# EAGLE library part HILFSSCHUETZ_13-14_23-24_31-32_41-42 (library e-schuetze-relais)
Hilfsschütz mit 2 Schließern, 2 Öffnern
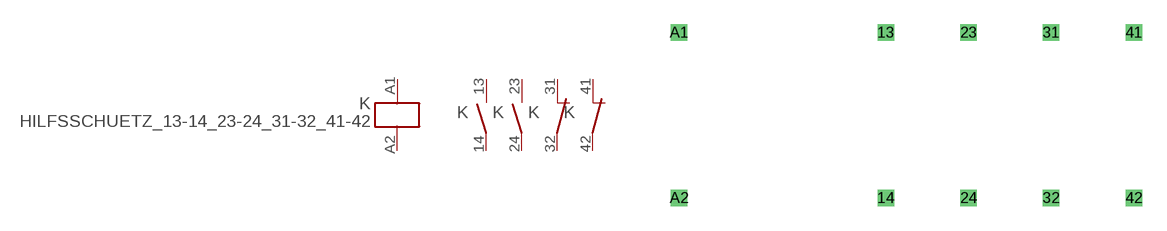
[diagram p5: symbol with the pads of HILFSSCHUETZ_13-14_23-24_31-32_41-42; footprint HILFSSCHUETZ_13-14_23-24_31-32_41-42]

Designator prefix K; gates G$1=SPULE 1=SCHLIESSER 2=SCHLIESSER 3=OEFFNER 4=OEFFNER

## HILFSSCHUETZ_13-14_23-24_31-32_41-42  [HILFSSCHUETZ_13-14_23-24_31-32_41-42]
13  1:3  pas
14  1:4  pas
23  2:3  pas
24  2:4  pas
31  3:1  pas
32  3:2  pas
41  4:1  pas
42  4:2  pas
A1  G$1:A1  in
A2  G$1:A2  in

## Footprint HILFSSCHUETZ_13-14_23-24_31-32_41-42 (pad centres in mm)
Dummy
drill 0.5 pad 1 square: 13 2.54,5.08; 14 2.54,-5.08; 23 7.62,5.08; 24 7.62,-5.08; 31 12.7,5.08; 32 12.7,-5.08; 41 17.78,5.08; 42 17.78,-5.08; A1 -10.16,5.08; A2 -10.16,-5.08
